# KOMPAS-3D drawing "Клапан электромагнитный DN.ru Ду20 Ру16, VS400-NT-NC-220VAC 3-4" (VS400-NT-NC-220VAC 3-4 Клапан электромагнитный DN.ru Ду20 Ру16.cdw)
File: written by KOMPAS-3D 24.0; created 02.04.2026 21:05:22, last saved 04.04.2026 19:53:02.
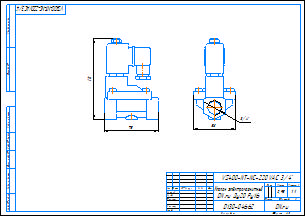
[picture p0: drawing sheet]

Document properties: c3d_UniqueCompID: ef56311e-7521-43dc-8291-0e6108b3d81d; Обозначение: VS400-ET-NC-220VAC 1-2; Наименование: Клапан электромагнитный DN.ru Ду15 Ру16; Автор: artio; Класс точности: c; Знак неуказанной шероховатости: Шероховатость не задана; Рассекать на разрезах: Да; c3d_UniqueCompID: ef56311e-7521-43dc-8291-0e6108b3d81d; Обозначение: VS400-ET-NC-220VAC 3-4; Наименование: Клапан электромагнитный DN.ru Ду20 Ру16; Автор: artio; Класс точности: c; Знак неуказанной шероховатости: Шероховатость не задана; Рассекать на разрезах: Да; c3d_UniqueCompID: ef56311e-7521-43dc-8291-0e6108b3d81d; Обозначение: VS400-ET-NC-220VAC 3-8; Наименование: Клапан электромагнитный DN.ru Ду10 Ру16; Автор: artio; Класс точности: c; Знак неуказанной шероховатости: Шероховатость не задана; Рассекать на разрезах: Да; Автор: artio; Форматы листов документа: A3; Полное имя файла: VS400-NT-NC-220VAC 3-4 Клапан электромагнитный DN.ru Ду20 Ру16.m3d; Масса: 0.954; Наименование: Клапан электромагнитный DN.ru Ду20 Ру16; Количество листов документа: 1; Примечание: D130-04662

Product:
- Body: Тело 1  | qty 1
    Масса: 1.210539
- Part/product: Клапан электромагнитный DN.ru Ду20 Ру16  | designation VS400-NT-NC-220VAC 3-4
    Масса: 0.954
    Раздел спецификации: Прочие изделия
    Примечание: D130-04662
    additional columns: ef56311e-7521-43dc-8291-0e6108b3d81d; VS400-ET-NC-220VAC 3-4; artio; c; Шероховатость не задана; Да

Views: Вид 1, Спереди, Проекционный вид 2
Referenced files in C:\Users\artio\OneDrive\Рабочий стол\Клапан электромагнитный DN.ru VS4x-xT-NC-x\DN10\: VS400-ET-NC-220VAC 3-8 Клапан электромагнитный DN.ru Ду10 Ру16.m3d, VS400-ET-NC-220VAC 3-8 Клапан электромагнитный DN.ru Ду10 Ру16.cdw
Referenced files in C:\Users\artio\OneDrive\Рабочий стол\Клапан электромагнитный DN.ru\VS400-NT-NC\VS400-NT-NC-220VAC\: VS400-NT-NC-220VAC 3-4 Клапан электромагнитный DN.ru Ду20 Ру16.m3d
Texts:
  VS400-NT-NC-220VAC 3-4
  Линейный размер
  Клапан электромагнитный
  DN.ru Ду20 Ру16
  VS400-NT-NC-220VAC 3/4"
  VS400-NT-NC-220VAC 3/4"-
  Клапан электромагнитный DN.ru Ду20 Ру16
  VS400-NT-NC-220VAC 3-4 Клапан электромагнитный DN.ru Ду20 Ру16
Dimensions and other numbers on the sheet: 0; 3; 2; 4; 58; 3/4"; 75; 112; 1:1; 1; 0,95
